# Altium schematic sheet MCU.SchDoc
size 292 x 193 mm; Author: Power Lin; DocumentNumber: 2; SheetNumber: 2; SheetTotal: 4; Website: wiki-power.com
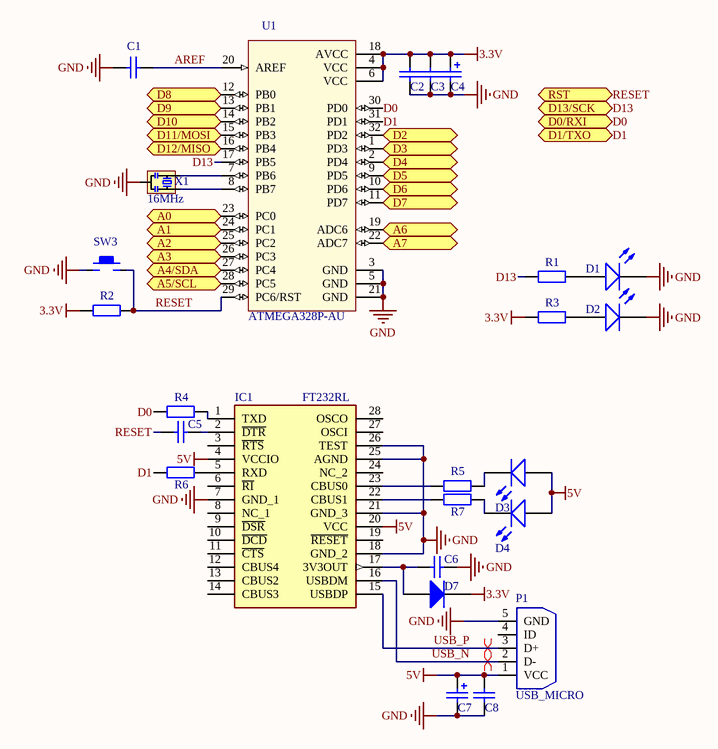
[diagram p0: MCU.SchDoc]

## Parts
C1  100nF  [CAP-0603]  (value not drawn)
C2  1uF  [CAP-0603]  (value not drawn)
C3  1uF  [CAP-0603]  (value not drawn)
C4  4.7uF 16V  [CAP-AUX-3216]  (value not drawn)
C5  100nF  [CAP-0603]  (value not drawn)
C6  100nF  [CAP-0603]  (value not drawn)
C7  4.7uF 16V  [CAP-AUX-3216]  (value not drawn)
C8  100nF  [CAP-0603]  (value not drawn)
D1  GREEN  [LED-0603]  (value not drawn)
D2  RED  [LED-0603]  (value not drawn)
D3  RED  [LED-0603]  (value not drawn)
D4  RED  [LED-0603]  (value not drawn)
D7  SS14  [SOD_123]  (value not drawn)
IC1  FT232RL  [SSOP]
P1  USB_MICRO  [Micro usb座 -全贴片]
R1  330R  [R-0603]  (value not drawn)
R2  1K  [R-0603]  (value not drawn)
R3  10K  [R-0603]  (value not drawn)
R4  1K  [R-0603]  (value not drawn)
R5  1K  [R-0603]  (value not drawn)
R6  1K  [R-0603]  (value not drawn)
R7  1K  [R-0603]  (value not drawn)
SW3  KEY  [KEY-4P-4.2*3.4*2.5]  (value not drawn)
U1  ATMEGA328P-AU  [TQFP-32_7x7x08P]
X1  16MHz  [CSTCE_G(A)村田晶振]

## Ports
A0 (bidir), A1 (bidir), A2 (bidir), A3 (bidir), A4/SDA (bidir), A5/SCL (bidir), A6 (bidir), A7 (bidir), D0/RXI (bidir), D1/TXO (bidir), D2 (bidir), D3 (bidir), D4 (bidir), D5 (bidir), D6 (bidir), D7 (bidir), D8 (bidir), D9 (bidir), D10 (bidir), D11/MOSI (bidir), D12/MISO (bidir), D13/SCK (bidir), RST (bidir)

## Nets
3.3V: C2.2 C3.2 C4.1 D7.2(K) R2.1 R3.1 U1.4(VCC) U1.6(VCC) U1.18(AVCC)
5V: C7.1 C8.2 D3.A D4.A IC1.4(VCCIO) IC1.20(VCC) P1.1(VCC)
GND: C1.1 C2.1 C3.1 C4.2 C6.1 C7.2 C8.1 D1.K D2.K IC1.7(GND_1) IC1.18(GND_2) IC1.21(GND_3) IC1.25(AGND) IC1.26(TEST) P1.5(GND) SW3.1 U1.3(GND) U1.5(GND) U1.21(GND) X1.2(GND)
A0: U1.23(PC0) ; port A0
A1: U1.24(PC1) ; port A1
A2: U1.25(PC2) ; port A2
A3: U1.26(PC3) ; port A3
A4/SDA: U1.27(PC4) ; port A4/SDA
A5/SCL: U1.28(PC5) ; port A5/SCL
A6: U1.19(ADC6) ; port A6
A7: U1.22(ADC7) ; port A7
AREF: C1.2 U1.20(AREF)
D0: R4.1 U1.30(PD0) ; port D0/RXI
D1: R6.1 U1.31(PD1) ; port D1/TXO
D2: U1.32(PD2) ; port D2
D3: U1.1(PD3) ; port D3
D4: U1.2(PD4) ; port D4
D5: U1.9(PD5) ; port D5
D6: U1.10(PD6) ; port D6
D7: U1.11(PD7) ; port D7
D8: U1.12(PB0) ; port D8
D9: U1.13(PB1) ; port D9
D10: U1.14(PB2) ; port D10
D11/MOSI: U1.15(PB3) ; port D11/MOSI
D12/MISO: U1.16(PB4) ; port D12/MISO
D13: R1.1 U1.17(PB5) ; port D13/SCK
RESET: C5.2 R2.2 SW3.2 U1.29(PC6/RST) ; port RST
USB_N: IC1.16(USBDM) P1.2(D-)
USB_P: IC1.15(USBDP) P1.3(D+)
NetC5_1: C5.1 IC1.2(~{DTR})
NetC6_2: C6.2 D7.1(A) IC1.17(3V3OUT)
NetD1_A: D1.A R1.2
NetD2_A: D2.A R3.2
NetD3_K: D3.K R5.2
NetD4_K: D4.K R7.2
NetIC1_1: IC1.1(TXD) R4.2
NetIC1_5: IC1.5(RXD) R6.2
NetIC1_22: IC1.22(CBUS1) R7.1
NetIC1_23: IC1.23(CBUS0) R5.1
NetU1_7: U1.7(PB6) X1.1(OSC1)
NetU1_8: U1.8(PB7) X1.3(OSC2)

Not connected (* = marked no-connect by the designer): IC1 3(~{RTS}) 6(~{RI}) 8(NC_1) 9(~{DSR}) 10(~{DCD}) 11(~{CTS}) 12(CBUS4) 13(CBUS2) 14(CBUS3) 19(~{RESET}) 24(NC_2) 27(OSCI) 28(OSCO); P1 4(ID)

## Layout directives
differential pair: USB_N, USB_P

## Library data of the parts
C1-C3 C5 C6 C8 = CAP: 贴片电容
C4 C7 = CAP-POL: 贴片电容-有极性
D1-D4 = LED: 发光二极管; pin to pad: A>1 K>2
D7 = DIODE: 二极管
IC1 = FT232RL: USB to UART; Manufacturer_Name: FTDI Chip
P1 = USB_MICRO: USB 接口
R1-R7 = RES: 贴片电阻
SW3 = KEY: 按键开关
U1 = ATMEGA328P-AU: 微控制器, 8 Bit, Atmega, 20mhz, Tqfp-32; MF: Microchip
X1 = XTAL: 有源晶振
